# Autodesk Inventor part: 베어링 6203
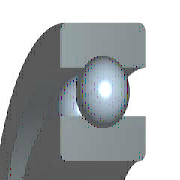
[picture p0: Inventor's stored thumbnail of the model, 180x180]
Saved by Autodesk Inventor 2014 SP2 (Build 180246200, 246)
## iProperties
IsCustomPart: 0
Created: 2014-10
Part Number: 베어링 6203
Material: 강철, 연강
Description: 깊은 그루브 볼 베어링
Document SubType Name: Modeling
Standard: KS B 2023
Designer: KYOUNG IL JANG
Standards Organization: KS
Language: ko-KR
Size Designation: 6203 - 17 x 40 x 12
Categories: <MemberInstance><Categories><Category DisplayName="샤프트 부품" InternalName="7f7aeb1f-a693-4053-b835-cee3144e0d98" Mnemonic="SHFT"><Category DisplayName="베어링" Inter
Density: 7.86 g/cm^3
Mass: 64.9809 g
Surface Area: 64.3582 cm^2
Volume: 8.26729 cm^3
Appearance: 노란색
Author: SeoGD™ [www.esajin.kr]
Revision Number: 1
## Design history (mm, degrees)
sketch "스케치" dims "d0" = 5.98 (= -0.26 x WD + 0.26 x BD)
  geometry: L1 (3.01, 14.25)-(8.99, 14.25); L2 (6, 14.25)-(6, 11.26); L3 (6, 14.25)-(6, 17.24); L4 (3.778, 12.249)-(0, 12.249); L5 (0, 8.5)-(12, 8.5); L6 (3.778, 16.251)-(0, 16.251); L7 (0, 20)-(12, 20); L8 (12, 8.5)-(12, 12.249); L9 (8.222, 12.249)-(12, 12.249); L10 (8.222, 16.251)-(12, 16.251); L11 (12, 20)-(12, 16.251); L12 (-1.4, 0)-(8.4, 0) reference; L13 (0, -0.3)-(0, 5.3) reference
  constraints: 22 end point, 4 point on line, 2 collinear, 2 perpendicular, 2 symmetric about line, 1 midpoint, 1 parallel, 14 other
  dimensions: "d9" = 17 diameter of L5 L12 (= WD); "d11" = 40 diameter of L7 L12 (= BD); "d12" = 12 distance between parallel lines of L8 L13 (= KB); "d13" = 24.498 diameter of L9 L12 (= 0.326 x BD + 0.674 x WD)
revolve "본체" stored, may be unused: angle "d6" = 90 deg
revolve "볼" stored, may be unused: angle "d7" = 90 deg
pattern_circular "IDS_ARRAYBALL[SIMPL:T]" dims angle "d3" = 360 deg
body "Solid1"
fillet "모깎기1" dims "d1" = 0.6 (= KRS)
other parameters: "WD" = 17 [user parameter; used in 5 equation terms], "BD" = 40 [user parameter; used in 5 equation terms], "KB" = 12 [user parameter; used in 1 equation term], "KRS" = 0.6 [user parameter; used in 1 equation term], "d4" = 0, "d5" = 0, "d8" = 0, "d14" = 0, "d15" = 0, "BBA" = 0 [user parameter], "BC0" = 4750000 [user parameter], "BC" = 9560000 [user parameter], "WR" = 8.5 (= 0.5 x WD) [user parameter]
